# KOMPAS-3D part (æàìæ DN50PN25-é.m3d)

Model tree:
1. Объединить компоненты:1  (labels: СЕНС DN50PN25-В)

Referenced files in D:\Савин\!СЕНСОР\3D для заказчика\!Новый перечень\СЕНС\3. СЕНС-В\DN50\: СЕНС DN50PN25-В.a3d
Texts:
  СЕНС DN50PN25-В
  ООО НПП Сенсор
